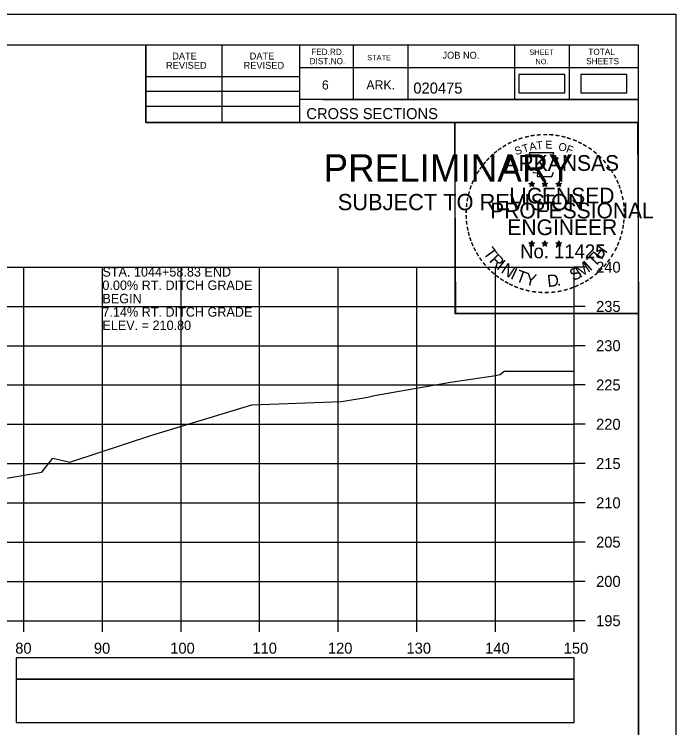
# Model space of a CAD drawing. Extents: x 1386544 to 1388153, y 379785 to 390999.
# Drawn here: x 1387438.5 to 1387522.6, y 387068 to 387158.9 of the extents above; entities that cross this region are included whole.
import ezdxf

# ---------------------------------------------------------------- set-up
doc = ezdxf.new("R2010")
doc.units = 0
for name, color, linetype in [('R_Axis', 7, 'Continuous'), ('R_Axis Annot', 7, 'Continuous'), ('R_Border', 7, 'Continuous'), ('R_Border PE', 7, 'Continuous'), ('R_Border Prem', 7, 'Continuous'), ('R_Exist Surface', 7, 'Continuous'), ('R_Fin Surface Annot', 7, 'Continuous'), ('R_Grid', 7, 'Continuous'), ('R_No Plot', 7, 'Continuous'), ('S_SHOULDER', 7, 'Continuous')]:
    doc.layers.add(name, color=color, linetype=linetype)

msp = doc.modelspace()

# ---------------------------------------------------------------- linework, layer by layer
at = {"layer": 'R_Axis'}
for p, q in [((1387509.676, 387081.667), (1387509.676, 387126.667)), ((1387511.076, 387126.667), (1387509.676, 387126.667)), ((1387511.076, 387121.667), (1387509.676, 387121.667)), ((1387511.076, 387116.667), (1387509.676, 387116.667)), ((1387511.076, 387111.667), (1387509.676, 387111.667)), ((1387511.076, 387106.667), (1387509.676, 387106.667)), ((1387511.076, 387101.667), (1387509.676, 387101.667)), ((1387511.076, 387096.667), (1387509.676, 387096.667)), ((1387511.076, 387091.667), (1387509.676, 387091.667)), ((1387511.076, 387086.667), (1387509.676, 387086.667)), ((1387209.676, 387081.667), (1387509.676, 387081.667)), ((1387439.676, 387080.267), (1387439.676, 387081.667)), ((1387449.676, 387080.267), (1387449.676, 387081.667)), ((1387459.676, 387080.267), (1387459.676, 387081.667)), ((1387469.676, 387080.267), (1387469.676, 387081.667)), ((1387479.676, 387080.267), (1387479.676, 387081.667)), ((1387489.676, 387080.267), (1387489.676, 387081.667)), ((1387499.676, 387080.267), (1387499.676, 387081.667)), ((1387509.676, 387080.267), (1387509.676, 387081.667)), ((1387511.076, 387081.667), (1387509.676, 387081.667))]:
    msp.add_line(p, q, dxfattribs=at)
at = {"layer": 'R_Axis Annot'}
for points in [[(1387438.697, 387074.223), (1387509.676, 387074.223), (1387509.676, 387076.932), (1387438.697, 387076.932)], [(1387438.697, 387068.696), (1387509.676, 387068.696), (1387509.676, 387074.223), (1387438.697, 387074.223)]]:
    msp.add_lwpolyline(points, close=True, dxfattribs=at)
at = {"layer": 'R_Border'}
for p, q in [((1387201.676, 387154.961), (1387517.856, 387154.961)), ((1387455.216, 387145.081), (1387455.216, 387154.961)), ((1387464.896, 387145.081), (1387464.896, 387154.961)), ((1387474.756, 387154.961), (1387474.756, 387145.081)), ((1387481.596, 387154.961), (1387481.596, 387148.021)), ((1387488.536, 387154.961), (1387488.536, 387148.021)), ((1387502.116, 387154.961), (1387502.116, 387148.021)), ((1387509.056, 387154.961), (1387509.056, 387148.021)), ((1387517.856, 386949.501), (1387517.856, 387154.961)), ((1387517.856, 387152.021), (1387474.756, 387152.021)), ((1387517.856, 387152.041), (1387517.856, 387152.041)), ((1387455.216, 387150.941), (1387474.756, 387150.941)), ((1387455.216, 387149.081), (1387474.756, 387149.081)), ((1387517.856, 387148.021), (1387474.756, 387148.021)), ((1387477.716, 387148.021), (1387517.856, 387148.021)), ((1387455.216, 387147.141), (1387474.756, 387147.141)), ((1387517.856, 387145.081), (1387455.216, 387145.081))]:
    msp.add_line(p, q, dxfattribs=at)
at = {"layer": 'R_Border PE'}
for p, q in [((1387503.941, 387137.336), (1387504.29, 387137.225)), ((1387503.941, 387137.336), (1387504.194, 387137.291)), ((1387503.941, 387137.336), (1387504.178, 387137.214)), ((1387504.074, 387136.928), (1387504.29, 387137.225)), ((1387504.074, 387136.928), (1387504.2, 387137.172)), ((1387504.074, 387136.928), (1387504.288, 387137.145)), ((1387504.29, 387137.59), (1387504.249, 387137.338)), ((1387504.503, 387136.928), (1387504.288, 387137.142)), ((1387504.29, 387137.225), (1387504.29, 387137.59)), ((1387504.29, 387137.59), (1387504.339, 387137.34)), ((1387504.637, 387137.336), (1387504.29, 387137.225)), ((1387504.503, 387136.928), (1387504.29, 387137.225)), ((1387504.637, 387137.336), (1387504.351, 387137.287)), ((1387504.503, 387136.928), (1387504.366, 387137.219)), ((1387504.637, 387137.336), (1387504.433, 387137.234)), ((1387505.611, 387137.336), (1387505.96, 387137.225)), ((1387505.611, 387137.336), (1387505.864, 387137.291)), ((1387505.611, 387137.336), (1387505.848, 387137.214)), ((1387505.744, 387136.928), (1387505.96, 387137.225)), ((1387505.744, 387136.928), (1387505.87, 387137.172)), ((1387505.744, 387136.928), (1387505.958, 387137.145)), ((1387505.96, 387137.59), (1387505.919, 387137.338)), ((1387506.173, 387136.928), (1387505.958, 387137.142)), ((1387505.96, 387137.225), (1387505.96, 387137.59)), ((1387505.96, 387137.59), (1387506.009, 387137.34)), ((1387506.307, 387137.336), (1387505.96, 387137.225)), ((1387506.173, 387136.928), (1387505.96, 387137.225)), ((1387506.307, 387137.336), (1387506.021, 387137.287)), ((1387506.173, 387136.928), (1387506.036, 387137.219)), ((1387506.307, 387137.336), (1387506.103, 387137.234)), ((1387507.375, 387137.324), (1387507.724, 387137.213)), ((1387507.375, 387137.324), (1387507.628, 387137.279)), ((1387507.375, 387137.324), (1387507.612, 387137.202)), ((1387507.508, 387136.916), (1387507.724, 387137.213)), ((1387507.508, 387136.916), (1387507.634, 387137.16)), ((1387507.508, 387136.916), (1387507.722, 387137.133)), ((1387507.724, 387137.578), (1387507.683, 387137.326)), ((1387507.937, 387136.916), (1387507.722, 387137.13)), ((1387507.724, 387137.213), (1387507.724, 387137.578)), ((1387507.724, 387137.578), (1387507.773, 387137.328)), ((1387508.071, 387137.324), (1387507.724, 387137.213)), ((1387507.937, 387136.916), (1387507.724, 387137.213)), ((1387508.071, 387137.324), (1387507.785, 387137.275)), ((1387507.937, 387136.916), (1387507.8, 387137.207)), ((1387508.071, 387137.324), (1387507.867, 387137.222)), ((1387503.937, 387129.763), (1387504.286, 387129.652)), ((1387503.937, 387129.763), (1387504.19, 387129.718)), ((1387503.937, 387129.763), (1387504.174, 387129.641)), ((1387504.07, 387129.355), (1387504.286, 387129.652)), ((1387504.07, 387129.355), (1387504.196, 387129.599)), ((1387504.07, 387129.355), (1387504.284, 387129.572)), ((1387504.286, 387130.017), (1387504.245, 387129.765)), ((1387504.499, 387129.355), (1387504.284, 387129.569)), ((1387504.286, 387129.652), (1387504.286, 387130.017)), ((1387504.286, 387130.017), (1387504.335, 387129.767)), ((1387504.633, 387129.763), (1387504.286, 387129.652)), ((1387504.499, 387129.355), (1387504.286, 387129.652)), ((1387504.633, 387129.763), (1387504.347, 387129.714)), ((1387504.499, 387129.355), (1387504.362, 387129.646)), ((1387504.633, 387129.763), (1387504.429, 387129.661)), ((1387505.606, 387129.763), (1387505.955, 387129.652)), ((1387505.606, 387129.763), (1387505.859, 387129.718)), ((1387505.606, 387129.763), (1387505.843, 387129.641)), ((1387505.739, 387129.355), (1387505.955, 387129.652)), ((1387505.739, 387129.355), (1387505.865, 387129.599)), ((1387505.739, 387129.355), (1387505.953, 387129.572)), ((1387505.955, 387130.017), (1387505.914, 387129.765)), ((1387506.168, 387129.355), (1387505.953, 387129.569)), ((1387505.955, 387129.652), (1387505.955, 387130.017)), ((1387505.955, 387130.017), (1387506.004, 387129.767)), ((1387506.302, 387129.763), (1387505.955, 387129.652)), ((1387506.168, 387129.355), (1387505.955, 387129.652)), ((1387506.302, 387129.763), (1387506.016, 387129.714)), ((1387506.168, 387129.355), (1387506.031, 387129.646)), ((1387506.302, 387129.763), (1387506.098, 387129.661)), ((1387507.373, 387129.753), (1387507.722, 387129.642)), ((1387507.373, 387129.753), (1387507.626, 387129.708)), ((1387507.373, 387129.753), (1387507.61, 387129.631)), ((1387507.506, 387129.345), (1387507.722, 387129.642)), ((1387507.506, 387129.345), (1387507.632, 387129.589)), ((1387507.506, 387129.345), (1387507.72, 387129.562)), ((1387507.722, 387130.007), (1387507.681, 387129.755)), ((1387507.935, 387129.345), (1387507.72, 387129.559)), ((1387507.722, 387129.642), (1387507.722, 387130.007)), ((1387507.722, 387130.007), (1387507.771, 387129.757)), ((1387508.069, 387129.753), (1387507.722, 387129.642)), ((1387507.935, 387129.345), (1387507.722, 387129.642)), ((1387508.069, 387129.753), (1387507.783, 387129.704)), ((1387507.935, 387129.345), (1387507.798, 387129.636)), ((1387508.069, 387129.753), (1387507.865, 387129.651))]:
    msp.add_line(p, q, dxfattribs=at)
for points in [[(1387503.982, 387141.214), (1387504.251, 387140.387)], [(1387507.493, 387140.292), (1387507.635, 387140.576), (1387506.95, 387140.552), (1387507.098, 387141.214), (1387503.982, 387141.214)], [(1387504.474, 387138.791), (1387504.474, 387138.704), (1387505.037, 387138.685), (1387504.983, 387138.212), (1387506.853, 387138.212), (1387507.054, 387138.748)], [(1387504.29, 387137.59), (1387504.503, 387136.928), (1387503.941, 387137.336), (1387504.637, 387137.336), (1387504.074, 387136.928), (1387504.29, 387137.59)], [(1387505.96, 387137.59), (1387506.173, 387136.928), (1387505.611, 387137.336), (1387506.307, 387137.336), (1387505.744, 387136.928), (1387505.96, 387137.59)], [(1387507.724, 387137.578), (1387507.937, 387136.916), (1387507.375, 387137.324), (1387508.071, 387137.324), (1387507.508, 387136.916), (1387507.724, 387137.578)], [(1387504.286, 387130.017), (1387504.499, 387129.355), (1387503.937, 387129.763), (1387504.633, 387129.763), (1387504.07, 387129.355), (1387504.286, 387130.017)], [(1387505.955, 387130.017), (1387506.168, 387129.355), (1387505.606, 387129.763), (1387506.302, 387129.763), (1387505.739, 387129.355), (1387505.955, 387130.017)], [(1387507.722, 387130.007), (1387507.935, 387129.345), (1387507.373, 387129.753), (1387508.069, 387129.753), (1387507.506, 387129.345), (1387507.722, 387130.007)]]:
    msp.add_lwpolyline(points, dxfattribs=at)
for centre, radius in [((1387504.289, 387137.224), 0.172), ((1387504.289, 387137.224), 0.145), ((1387504.289, 387137.224), 0.116), ((1387504.289, 387137.224), 0.0991), ((1387504.289, 387137.224), 0.0747), ((1387504.289, 387137.224), 0.0495), ((1387504.289, 387137.224), 0.0296), ((1387505.959, 387137.224), 0.172), ((1387505.959, 387137.224), 0.145), ((1387505.959, 387137.224), 0.116), ((1387505.959, 387137.224), 0.0991), ((1387505.959, 387137.224), 0.0747), ((1387505.959, 387137.224), 0.0495), ((1387505.959, 387137.224), 0.0296), ((1387507.723, 387137.212), 0.172), ((1387507.723, 387137.212), 0.145), ((1387507.723, 387137.212), 0.116), ((1387507.723, 387137.212), 0.0991), ((1387507.723, 387137.212), 0.0747), ((1387507.723, 387137.212), 0.0495), ((1387507.723, 387137.212), 0.0296), ((1387504.285, 387129.651), 0.172), ((1387504.285, 387129.651), 0.145), ((1387504.285, 387129.651), 0.116), ((1387504.285, 387129.651), 0.0991), ((1387504.285, 387129.651), 0.0747), ((1387504.285, 387129.651), 0.0495), ((1387504.285, 387129.651), 0.0296), ((1387505.954, 387129.651), 0.172), ((1387505.954, 387129.651), 0.145), ((1387505.954, 387129.651), 0.116), ((1387505.954, 387129.651), 0.0991), ((1387505.954, 387129.651), 0.0747), ((1387505.954, 387129.651), 0.0495), ((1387505.954, 387129.651), 0.0296), ((1387507.721, 387129.641), 0.172), ((1387507.721, 387129.641), 0.145), ((1387507.721, 387129.641), 0.116), ((1387507.721, 387129.641), 0.0991), ((1387507.721, 387129.641), 0.0747), ((1387507.721, 387129.641), 0.0495), ((1387507.721, 387129.641), 0.0296)]:
    msp.add_circle(centre, radius, dxfattribs=at)
at = {"layer": 'R_Exist Surface'}
msp.add_lwpolyline([(1387436.743, 387099.689), (1387441.971, 387100.563), (1387443.37, 387102.366), (1387445.542, 387101.849), (1387455.96, 387105.27), (1387468.668, 387109.144), (1387480.109, 387109.586), (1387483.435, 387110.113), (1387484.284, 387110.326), (1387493.948, 387112.039), (1387499.408, 387112.827), (1387500.267, 387113.022), (1387500.795, 387113.445), (1387509.676, 387113.443)], dxfattribs=at)
at = {"layer": 'R_Grid'}
for p, q in [((1387209.676, 387126.667), (1387509.676, 387126.667)), ((1387439.676, 387081.667), (1387439.676, 387126.667)), ((1387449.676, 387081.667), (1387449.676, 387126.667)), ((1387459.676, 387081.667), (1387459.676, 387126.667)), ((1387469.676, 387081.667), (1387469.676, 387126.667)), ((1387479.676, 387081.667), (1387479.676, 387126.667)), ((1387489.676, 387081.667), (1387489.676, 387126.667)), ((1387499.676, 387081.667), (1387499.676, 387126.667)), ((1387509.676, 387081.667), (1387509.676, 387126.667)), ((1387209.676, 387121.667), (1387509.676, 387121.667)), ((1387209.676, 387116.667), (1387509.676, 387116.667)), ((1387209.676, 387111.667), (1387509.676, 387111.667)), ((1387209.676, 387106.667), (1387509.676, 387106.667)), ((1387209.676, 387101.667), (1387509.676, 387101.667)), ((1387209.676, 387096.667), (1387509.676, 387096.667)), ((1387209.676, 387091.667), (1387509.676, 387091.667)), ((1387209.676, 387086.667), (1387509.676, 387086.667)), ((1387209.676, 387081.667), (1387509.676, 387081.667))]:
    msp.add_line(p, q, dxfattribs=at)
at = {"layer": 'R_No Plot'}
for p, q in [((1387189.275, 387158.855), (1387522.609, 387158.855)), ((1387493.89, 387122.625), (1387493.89, 387122.625))]:
    msp.add_line(p, q, dxfattribs=at)
for points in [[(1387189.269, 387158.855), (1387522.609, 387158.855), (1387522.609, 386945.518), (1387189.269, 386945.518)], [(1387435.596, 387154.961), (1387455.216, 387154.961), (1387455.216, 387145.081), (1387471.328, 387145.081), (1387494.528, 387145.081), (1387494.528, 387120.748), (1387517.856, 387120.748), (1387517.856, 386949.501), (1387201.676, 386949.501), (1387201.676, 387154.961)], [(1387494.528, 387145.081), (1387517.735, 387145.081), (1387517.856, 387120.748), (1387494.648, 387120.748)]]:
    msp.add_lwpolyline(points, close=True, dxfattribs=at)
at = {"layer": 'S_SHOULDER'}
for points in [[(1387502.669, 387148.866), (1387508.503, 387148.866), (1387508.503, 387151.176), (1387502.669, 387151.176)], [(1387510.539, 387148.866), (1387516.373, 387148.866), (1387516.373, 387151.176), (1387510.539, 387151.176)]]:
    msp.add_lwpolyline(points, close=True, dxfattribs=at)

# ---------------------------------------------------------------- texts
at = {"layer": 'R_Axis Annot'}
for s, p in [('240', (1387512.476, 387125.967)), ('235', (1387512.476, 387120.967)), ('230', (1387512.476, 387115.967)), ('225', (1387512.476, 387110.967)), ('220', (1387512.476, 387105.967)), ('215', (1387512.476, 387100.967)), ('210', (1387512.476, 387095.967)), ('205', (1387512.476, 387090.967)), ('200', (1387512.476, 387085.967)), ('195', (1387512.476, 387080.967)), ('80', (1387438.59, 387077.467)), ('90', (1387448.59, 387077.467)), ('100', (1387458.304, 387077.467)), ('110', (1387468.756, 387077.467)), ('120', (1387478.359, 387077.467)), ('130', (1387488.359, 387077.467)), ('140', (1387498.359, 387077.467)), ('150', (1387508.359, 387077.467))]:
    msp.add_text(s, height=1.4, dxfattribs=at).set_placement(p)
at = {"layer": 'R_Border'}
for s, height, p in [('FED.RD.', 0.7819, (1387476.236, 387153.681)), ('JOB NO.', 0.8792, (1387492.936, 387153.201)), ('SHEET', 0.684, (1387503.976, 387153.681)), ('TOTAL', 0.7819, (1387511.496, 387153.681)), ('DATE', 0.8792, (1387458.554, 387153.097)), ('DATE', 0.8792, (1387468.414, 387153.097)), ('DIST.NO.', 0.7819, (1387476.036, 387152.501)), ('STATE', 0.684, (1387483.356, 387153.001)), ('NO.', 0.684, (1387504.756, 387152.501)), ('SHEETS', 0.7819, (1387511.216, 387152.501)), ('REVISED', 0.8792, (1387457.774, 387151.917)), ('REVISED', 0.8792, (1387467.634, 387151.917)), ('6', 1.172, (1387477.596, 387149.281)), ('ARK.', 1.1723, (1387483.256, 387149.281)), ('020475', 1.4, (1387489.232, 387148.76)), ('CROSS SECTIONS', 1.4, (1387475.62, 387145.511))]:
    msp.add_text(s, height=height, rotation=360, dxfattribs=at).set_placement(p)
at = {"layer": 'R_Border PE'}
for s, height, rotation, p in [('-', 1.6, 19.17608, (1387502.73, 387142.341)), ('-', 1.6, 13.63015, (1387503.48, 387142.582)), ('-', 1.6, 10.21935, (1387504.158, 387142.744)), ('-', 1.6, 5.89682, (1387504.887, 387142.854)), ('-', 1.6, 0.18623, (1387505.659, 387142.926)), ('-', 1.6, 357.74304, (1387506.382, 387142.913)), ('-', 1.6, 352.16172, (1387507.126, 387142.857)), ('-', 1.6, 347.20489, (1387507.845, 387142.743)), ('-', 1.6, 342.3362, (1387508.48, 387142.588)), ('-', 1.6, 34.06357, (1387500.866, 387141.385)), ('-', 1.6, 28.79182, (1387501.463, 387141.755)), ('-', 1.6, 24.30721, (1387502.096, 387142.072)), ('T', 1, 16.4036, (1387503.251, 387141.223)), ('A', 1, 11.21318, (1387504.077, 387141.474)), ('T', 1, 6.02276, (1387504.926, 387141.64)), ('E', 1, 0.83234, (1387506.031, 387141.75)), ('O', 1, 350.4515, (1387507.635, 387141.54)), ('-', 1.6, 337.85509, (1387509.215, 387142.365)), ('-', 1.6, 334.12109, (1387509.846, 387142.094)), ('-', 1.6, 329.64089, (1387510.425, 387141.811)), ('-', 1.6, 38.95066, (1387499.812, 387140.612)), ('-', 1.6, 36.23174, (1387500.288, 387140.99)), ('S', 1, 21.59401, (1387502.337, 387140.892)), ('F', 1, 340.07066, (1387508.589, 387141.312)), ('-', 1.6, 325.86266, (1387511.068, 387141.45)), ('-', 1.6, 320.52971, (1387511.678, 387141.024)), ('-', 1.6, 48.42305, (1387498.931, 387139.717)), ('-', 1.6, 42.96224, (1387499.379, 387140.195)), ('ARKANSAS', 2, 360, (1387500.835, 387138.926)), ('-', 1.6, 315.57859, (1387512.277, 387140.536)), ('-', 1.6, 54.23247, (1387498.115, 387138.664)), ('-', 1.6, 50.61417, (1387498.528, 387139.231)), ('-', 1.6, 309.87973, (1387512.846, 387139.986)), ('-', 1.6, 306.65218, (1387513.371, 387139.384)), ('-', 1.6, 58.07063, (1387497.79, 387138.137)), ('-', 1.4, 303.67529, (1387513.857, 387138.816)), ('-', 1.6, 67.77427, (1387497.218, 387136.912)), ('-', 1.6, 62.87135, (1387497.477, 387137.523)), ('-', 1.6, 299.66835, (1387514.176, 387138.209)), ('-', 1.6, 294.66279, (1387514.5, 387137.597)), ('-', 1.6, 72.39447, (1387496.999, 387136.282)), ('LICENSED', 2, 360, (1387501.432, 387134.777)), ('DWB', 0.01, 360, (1387504.277, 387137.22)), ('DWB', 0.01, 360, (1387505.947, 387137.22)), ('DWB', 0.01, 360, (1387507.711, 387137.209)), ('-', 1.6, 290.57283, (1387514.757, 387137.02)), ('-', 1.6, 75.46096, (1387496.802, 387135.568)), ('-', 1.6, 285.12326, (1387514.991, 387136.44)), ('-', 1.6, 81.20126, (1387496.67, 387134.855)), ('-', 1.6, 280.54934, (1387515.191, 387135.698)), ('-', 1.6, 89.06224, (1387496.569, 387133.463)), ('-', 1.6, 85.18634, (1387496.594, 387134.164)), ('PROFESSIONAL', 2, 360, (1387499.009, 387132.873)), ('-', 1.6, 276.59616, (1387515.353, 387134.93)), ('-', 1.6, 274.33011, (1387515.413, 387134.208)), ('-', 1.6, 94.19588, (1387496.604, 387132.738)), ('-', 1.6, 269.94067, (1387515.447, 387133.576)), ('-', 1.6, 98.94793, (1387496.676, 387132.071)), ('ENGINEER', 2, 360, (1387501.196, 387130.748)), ('-', 1.6, 263.5172, (1387515.428, 387132.91)), ('-', 1.6, 101.71495, (1387496.811, 387131.338)), ('-', 1.6, 255.7626, (1387515.247, 387131.578)), ('-', 1.6, 260.99529, (1387515.357, 387132.256)), ('-', 1.6, 105.45785, (1387496.973, 387130.743)), ('-', 1.6, 109.08742, (1387497.188, 387130.112)), ('-', 1.6, 252.86809, (1387515.066, 387130.858)), ('-', 1.6, 114.06432, (1387497.442, 387129.516)), ('No. 11425', 1.757, 360, (1387502.823, 387127.797)), ('DWB', 0.01, 360, (1387504.273, 387129.647)), ('DWB', 0.01, 360, (1387505.942, 387129.647)), ('DWB', 0.01, 360, (1387507.709, 387129.637)), ('-', 1.6, 247.88866, (1387514.843, 387130.185)), ('-', 1.6, 115.72885, (1387497.747, 387128.898)), ('T', 1.54, 306.04056, (1387498.046, 387128.49)), ('H', 1.54, 54.60883, (1387513.166, 387127.525)), ('-', 1.6, 244.61971, (1387514.581, 387129.556)), ('-', 1.6, 120.44712, (1387498.104, 387128.312)), ('-', 1.6, 125.89344, (1387498.507, 387127.751)), ('R', 1.54, 314.00497, (1387498.808, 387127.442)), ('T', 1.54, 46.64442, (1387512.276, 387126.583)), ('-', 1.6, 233.84524, (1387513.785, 387128.151)), ('-', 1.6, 239.07125, (1387514.187, 387128.804)), ('-', 1.6, 130.71812, (1387498.969, 387127.199)), ('I', 1.54, 321.96938, (1387499.709, 387126.51)), ('N', 1.54, 326.50021, (1387500.276, 387126.039)), ('M', 1.54, 32.65632, (1387510.43, 387125.258)), ('I', 1.54, 42.11359, (1387511.715, 387126.105)), ('-', 1.6, 231.25377, (1387513.355, 387127.585)), ('-', 1.6, 134.22381, (1387499.486, 387126.654)), ('-', 1.6, 138.93382, (1387500.011, 387126.19)), ('I', 1.54, 335.36034, (1387501.484, 387125.253)), ('T', 1.54, 339.89117, (1387502.145, 387124.925)), ('Y', 1.54, 347.85558, (1387503.362, 387124.48)), ('S', 1.54, 26.9312, (1387509.592, 387124.852)), ('-', 1.6, 221.08509, (1387512.354, 387126.512)), ('-', 1.6, 225.76533, (1387512.876, 387127.021)), ('-', 1.6, 144.64634, (1387500.567, 387125.784)), ('-', 1.6, 148.08978, (1387501.128, 387125.413)), ('D', 1.54, 6.39691, (1387506.347, 387124.121)), ('-', 1.6, 212.24909, (1387511.271, 387125.653)), ('-', 1.6, 215.73633, (1387511.805, 387126.04)), ('-', 1.6, 151.57039, (1387501.707, 387125.088)), ('-', 1.6, 154.60019, (1387502.229, 387124.841)), ('-', 1.6, 158.56121, (1387502.853, 387124.587)), ('-', 1.6, 162.79826, (1387503.54, 387124.374)), ('.', 1.54, 13.76417, (1387507.539, 387124.249)), ('-', 1.6, 200.71842, (1387509.47, 387124.715)), ('-', 1.6, 204.25161, (1387510.089, 387124.988)), ('-', 1.6, 207.35684, (1387510.713, 387125.307)), ('-', 1.6, 167.55551, (1387504.255, 387124.21)), ('-', 1.6, 173.11546, (1387505.027, 387124.1)), ('-', 1.6, 176.51827, (1387505.775, 387124.047)), ('-', 1.6, 181.59176, (1387506.519, 387124.066)), ('-', 1.6, 185.81666, (1387507.328, 387124.142)), ('-', 1.6, 191.28576, (1387508.064, 387124.274)), ('-', 1.6, 195.47429, (1387508.793, 387124.473))]:
    msp.add_text(s, height=height, rotation=rotation, dxfattribs=at).set_placement(p)
at = {"layer": 'R_Border Prem'}
for s, height, p in [('PRELIMINARY', 3.5, (1387477.807, 387137.544)), ('DWB', 0.01, (1387478.554, 387139.393)), ('SUBJECT TO REVISION', 2.07511, (1387479.616, 387133.915))]:
    msp.add_text(s, height=height, rotation=360, dxfattribs=at).set_placement(p)
at = {"layer": 'R_Fin Surface Annot'}
for s, p in [('STA. 1044+58.83 END', (1387449.676, 387125.467)), ('0.00% RT. DITCH GRADE', (1387449.676, 387123.767)), ('BEGIN', (1387449.676, 387122.067)), ('7.14% RT. DITCH GRADE', (1387449.676, 387120.367)), ('ELEV. = 210.80', (1387449.676, 387118.667))]:
    msp.add_text(s, height=1.2, dxfattribs=at).set_placement(p)

doc.saveas('drawing.dxf')
